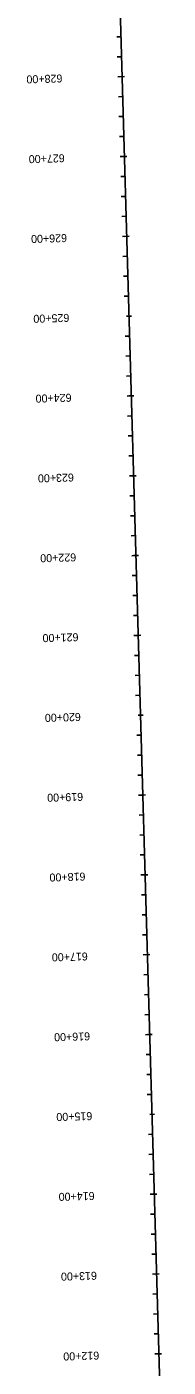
# Model space of a CAD drawing. Extents: x 23417911 to 23421158, y 6737892 to 6791804.
# Drawn here: x 23420652 to 23420830, y 6786753 to 6788431 of the extents above; entities that cross this region are included whole.
import ezdxf

# ---------------------------------------------------------------- set-up
doc = ezdxf.new("R2010")
doc.units = 0
for name, color, linetype in [('Alignment', 7, 'Continuous'), ('TextAlignmentLrg', 7, 'Continuous'), ('TextAlignmentSml', 7, 'Continuous')]:
    doc.layers.add(name, color=color, linetype=linetype)

msp = doc.modelspace()

# ---------------------------------------------------------------- linework, layer by layer
at = {"layer": 'Alignment'}
msp.add_line((23420829.7, 6786372.7), (23420747.3, 6789225.4), dxfattribs=at)
msp.add_line((23420829.7, 6786372.7), (23420747.3, 6789225.4), dxfattribs=at)
at = {"layer": 'TextAlignmentLrg'}
for p, q in [((23420772, 6788369.1), (23420766.5, 6788368.9)), ((23420774.9, 6788269.1), (23420769.4, 6788269)), ((23420777.8, 6788169.2), (23420772.3, 6788169)), ((23420777.6, 6788069.1), (23420783.7, 6788069.3)), ((23420783.6, 6787969.3), (23420778.1, 6787969.1)), ((23420786.4, 6787869.3), (23420781, 6787869.2)), ((23420789.3, 6787769.4), (23420783.9, 6787769.2)), ((23420792.2, 6787669.4), (23420786.8, 6787669.2)), ((23420792.1, 6787569.3), (23420798.2, 6787569.5)), ((23420798, 6787469.5), (23420792.5, 6787469.3)), ((23420800.9, 6787369.5), (23420795.4, 6787369.4)), ((23420803.8, 6787269.6), (23420798.3, 6787269.4)), ((23420806.7, 6787169.6), (23420801.2, 6787169.4)), ((23420806.5, 6787069.6), (23420812.6, 6787069.7)), ((23420812.4, 6786969.7), (23420807, 6786969.5)), ((23420815.3, 6786869.7), (23420809.9, 6786869.6)), ((23420818.2, 6786769.8), (23420812.8, 6786769.6))]:
    msp.add_line(p, q, dxfattribs=at)
at = {"layer": 'TextAlignmentSml'}
for p, q in [((23420770.6, 6788419.1), (23420765.1, 6788418.9)), ((23420771.3, 6788394.1), (23420765.8, 6788393.9)), ((23420768.9, 6788369), (23420775.1, 6788369.2)), ((23420772.7, 6788344.1), (23420767.3, 6788344)), ((23420773.5, 6788319.1), (23420768, 6788319)), ((23420774.2, 6788294.1), (23420768.7, 6788294)), ((23420771.8, 6788269.1), (23420778, 6788269.2)), ((23420775.6, 6788244.2), (23420770.2, 6788244)), ((23420776.3, 6788219.2), (23420770.9, 6788219)), ((23420777.1, 6788194.2), (23420771.6, 6788194)), ((23420774.7, 6788169.1), (23420780.8, 6788169.3)), ((23420778.5, 6788144.2), (23420773, 6788144)), ((23420779.2, 6788119.2), (23420773.8, 6788119.1)), ((23420779.9, 6788094.2), (23420774.5, 6788094.1)), ((23420777.6, 6788069.1), (23420783.7, 6788069.3)), ((23420781.4, 6788044.2), (23420775.9, 6788044.1)), ((23420782.1, 6788019.3), (23420776.7, 6788019.1)), ((23420782.8, 6787994.3), (23420777.4, 6787994.1)), ((23420780.5, 6787969.2), (23420786.6, 6787969.4)), ((23420784.3, 6787944.3), (23420778.8, 6787944.1)), ((23420785, 6787919.3), (23420779.5, 6787919.1)), ((23420785.7, 6787894.3), (23420780.3, 6787894.1)), ((23420783.4, 6787869.2), (23420789.5, 6787869.4)), ((23420787.2, 6787844.3), (23420781.7, 6787844.2)), ((23420787.9, 6787819.3), (23420782.4, 6787819.2)), ((23420788.6, 6787794.3), (23420783.2, 6787794.2)), ((23420786.3, 6787769.3), (23420792.4, 6787769.4)), ((23420790.1, 6787744.4), (23420784.6, 6787744.2)), ((23420790.8, 6787719.4), (23420785.3, 6787719.2)), ((23420791.5, 6787694.4), (23420786, 6787694.2)), ((23420789.2, 6787669.3), (23420795.3, 6787669.5)), ((23420792.9, 6787644.4), (23420787.5, 6787644.2)), ((23420793.7, 6787619.4), (23420788.2, 6787619.3)), ((23420794.4, 6787594.4), (23420788.9, 6787594.3)), ((23420792.1, 6787569.3), (23420798.2, 6787569.5)), ((23420795.8, 6787544.4), (23420790.4, 6787544.3)), ((23420796.6, 6787519.5), (23420791.1, 6787519.3)), ((23420797.3, 6787494.5), (23420791.8, 6787494.3)), ((23420794.9, 6787469.4), (23420801.1, 6787469.6)), ((23420798.7, 6787444.5), (23420793.3, 6787444.3)), ((23420799.4, 6787419.5), (23420794, 6787419.3)), ((23420800.2, 6787394.5), (23420794.7, 6787394.4)), ((23420797.8, 6787369.4), (23420804, 6787369.6)), ((23420801.6, 6787344.5), (23420796.2, 6787344.4)), ((23420802.3, 6787319.5), (23420796.9, 6787319.4)), ((23420803.1, 6787294.6), (23420797.6, 6787294.4)), ((23420800.7, 6787269.5), (23420806.8, 6787269.7)), ((23420804.5, 6787244.6), (23420799, 6787244.4)), ((23420805.2, 6787219.6), (23420799.8, 6787219.4)), ((23420805.9, 6787194.6), (23420800.5, 6787194.4)), ((23420803.6, 6787169.5), (23420809.7, 6787169.7)), ((23420807.4, 6787144.6), (23420801.9, 6787144.5)), ((23420808.1, 6787119.6), (23420802.7, 6787119.5)), ((23420808.8, 6787094.6), (23420803.4, 6787094.5)), ((23420806.5, 6787069.6), (23420812.6, 6787069.7)), ((23420810.3, 6787044.7), (23420804.8, 6787044.5)), ((23420811, 6787019.7), (23420805.5, 6787019.5)), ((23420811.7, 6786994.7), (23420806.3, 6786994.5)), ((23420809.4, 6786969.6), (23420815.5, 6786969.8)), ((23420813.2, 6786944.7), (23420807.7, 6786944.5)), ((23420813.9, 6786919.7), (23420808.4, 6786919.6)), ((23420814.6, 6786894.7), (23420809.2, 6786894.6)), ((23420812.3, 6786869.6), (23420818.4, 6786869.8)), ((23420816.1, 6786844.7), (23420810.6, 6786844.6)), ((23420816.8, 6786819.8), (23420811.3, 6786819.6)), ((23420817.5, 6786794.8), (23420812, 6786794.6)), ((23420815.2, 6786769.7), (23420821.3, 6786769.9))]:
    msp.add_line(p, q, dxfattribs=at)

# ---------------------------------------------------------------- texts
at = {"layer": 'TextAlignmentLrg'}
for s, p in [('625+00', (23420705.6, 6788072.1)), ('620+00', (23420720, 6787572.3)), ('615+00', (23420734.4, 6787072.5))]:
    msp.add_text(s, height=10.02, rotation=181.6554, dxfattribs=at).set_placement(p)
at = {"layer": 'TextAlignmentSml'}
for s, p in [('628+00', (23420696.9, 6788371.9)), ('627+00', (23420699.8, 6788272)), ('626+00', (23420702.7, 6788172)), ('625+00', (23420705.6, 6788072.1)), ('624+00', (23420708.4, 6787972.1)), ('623+00', (23420711.3, 6787872.2)), ('622+00', (23420714.2, 6787772.2)), ('621+00', (23420717.1, 6787672.2)), ('620+00', (23420720, 6787572.3)), ('619+00', (23420722.9, 6787472.3)), ('618+00', (23420725.8, 6787372.4)), ('617+00', (23420728.7, 6787272.4)), ('616+00', (23420731.6, 6787172.4)), ('615+00', (23420734.4, 6787072.5)), ('614+00', (23420737.3, 6786972.5)), ('613+00', (23420740.2, 6786872.6)), ('612+00', (23420743.1, 6786772.6))]:
    msp.add_text(s, height=10.02, rotation=181.6554, dxfattribs=at).set_placement(p)

doc.saveas('drawing.dxf')
